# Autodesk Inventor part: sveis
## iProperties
Created: 2009-07
Part Number: sveis
Document SubType Name: Modeling
Designer: TB
Mass: 26.5237 g
Surface Area: 107.919 cm^2
Volume: 26.5237 cm^3
Density: 1 g/cm^3
Author: TB
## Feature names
1. Extrusion1
